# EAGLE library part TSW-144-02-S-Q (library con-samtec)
THROUGH-HOLE .025" SQ POST HEADER Source: Samtec TSW.pdf
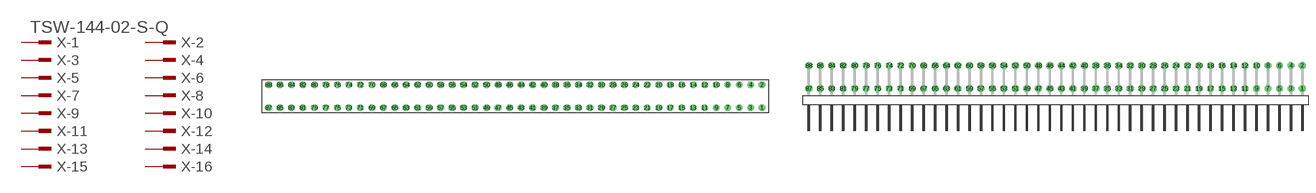
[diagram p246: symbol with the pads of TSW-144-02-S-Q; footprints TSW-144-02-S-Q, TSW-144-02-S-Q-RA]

Designator prefix X; gates -1=MPINV -2=MPIN -3=MPIN -4=MPIN -5=MPIN -6=MPIN -7=MPIN -8=MPIN -9=MPIN -10=MPIN -11=MPIN -12=MPIN -13=MPIN -14=MPIN -15=MPIN -16=MPIN -17=MPIN -18=MPIN -19=MPIN -20=MPIN -21=MPIN -22=MPIN -23=MPIN -24=MPIN -25=MPIN -26=MPIN -27=MPIN -28=MPIN -29=MPIN -30=MPIN -31=MPIN -32=MPIN -33=MPIN -34=MPIN -35=MPIN -36=MPIN -37=MPIN -38=MPIN -39=MPIN -40=MPIN -41=MPIN -42=MPIN -43=MPIN -44=MPIN -45=MPIN -46=MPIN -47=MPIN -48=MPIN -49=MPIN -50=MPIN -51=MPIN -52=MPIN -53=MPIN -54=MPIN -55=MPIN -56=MPIN -57=MPIN -58=MPIN -59=MPIN -60=MPIN -61=MPIN -62=MPIN -63=MPIN -64=MPIN -65=MPIN -66=MPIN -67=MPIN -68=MPIN -69=MPIN -70=MPIN -71=MPIN -72=MPIN -73=MPIN -74=MPIN -75=MPIN -76=MPIN -77=MPIN -78=MPIN -79=MPIN -80=MPIN -81=MPIN -82=MPIN -83=MPIN -84=MPIN -85=MPIN -86=MPIN -87=MPIN -88=MPIN

## TSW-144-02-S-Q (OC_FARNELL: unknown; OC_NEWARK: unknown)  [TSW-144-02-S-Q]
1  -1:1  pas
2  -2:1  pas
3  -3:1  pas
4  -4:1  pas
5  -5:1  pas
6  -6:1  pas
7  -7:1  pas
8  -8:1  pas
9  -9:1  pas
10  -10:1  pas
11  -11:1  pas
12  -12:1  pas
13  -13:1  pas
14  -14:1  pas
15  -15:1  pas
16  -16:1  pas
17  -17:1  pas
18  -18:1  pas
19  -19:1  pas
20  -20:1  pas
21  -21:1  pas
22  -22:1  pas
23  -23:1  pas
24  -24:1  pas
25  -25:1  pas
26  -26:1  pas
27  -27:1  pas
28  -28:1  pas
29  -29:1  pas
30  -30:1  pas
31  -31:1  pas
32  -32:1  pas
33  -33:1  pas
34  -34:1  pas
35  -35:1  pas
36  -36:1  pas
37  -37:1  pas
38  -38:1  pas
39  -39:1  pas
40  -40:1  pas
41  -41:1  pas
42  -42:1  pas
43  -43:1  pas
44  -44:1  pas
45  -45:1  pas
46  -46:1  pas
47  -47:1  pas
48  -48:1  pas
49  -49:1  pas
50  -50:1  pas
51  -51:1  pas
52  -52:1  pas
53  -53:1  pas
54  -54:1  pas
55  -55:1  pas
56  -56:1  pas
57  -57:1  pas
58  -58:1  pas
59  -59:1  pas
60  -60:1  pas
61  -61:1  pas
62  -62:1  pas
63  -63:1  pas
64  -64:1  pas
65  -65:1  pas
66  -66:1  pas
67  -67:1  pas
68  -68:1  pas
69  -69:1  pas
70  -70:1  pas
71  -71:1  pas
72  -72:1  pas
73  -73:1  pas
74  -74:1  pas
75  -75:1  pas
76  -76:1  pas
77  -77:1  pas
78  -78:1  pas
79  -79:1  pas
80  -80:1  pas
81  -81:1  pas
82  -82:1  pas
83  -83:1  pas
84  -84:1  pas
85  -85:1  pas
86  -86:1  pas
87  -87:1  pas
88  -88:1  pas

## TSW-144-02-S-Q-RA (OC_FARNELL: unknown; OC_NEWARK: unknown)  [TSW-144-02-S-Q-RA]
Pads as for TSW-144-02-S-Q

## Footprint TSW-144-02-S-Q (pad centres in mm)
THROUGH-HOLE .025" SQ POST HEADER Source: Samtec TSW.pdf
drill 1 pad 1.5 octagon: 1 54.61,-2.54; 2 54.61,2.54; 3 52.07,-2.54; 4 52.07,2.54; 5 49.53,-2.54; 6 49.53,2.54; 7 46.99,-2.54; 8 46.99,2.54; 9 44.45,-2.54; 10 44.45,2.54; 11 41.91,-2.54; 12 41.91,2.54; 13 39.37,-2.54; 14 39.37,2.54; 15 36.83,-2.54; 16 36.83,2.54; 17 34.29,-2.54; 18 34.29,2.54; 19 31.75,-2.54; 20 31.75,2.54; 21 29.21,-2.54; 22 29.21,2.54; 23 26.67,-2.54; 24 26.67,2.54; 25 24.13,-2.54; 26 24.13,2.54; 27 21.59,-2.54; 28 21.59,2.54; 29 19.05,-2.54; 30 19.05,2.54; 31 16.51,-2.54; 32 16.51,2.54; 33 13.97,-2.54; 34 13.97,2.54; 35 11.43,-2.54; 36 11.43,2.54; 37 8.89,-2.54; 38 8.89,2.54; 39 6.35,-2.54; 40 6.35,2.54; 41 3.81,-2.54; 42 3.81,2.54; 43 1.27,-2.54; 44 1.27,2.54; 45 -1.27,-2.54; 46 -1.27,2.54; 47 -3.81,-2.54; 48 -3.81,2.54; 49 -6.35,-2.54; 50 -6.35,2.54; 51 -8.89,-2.54; 52 -8.89,2.54; 53 -11.43,-2.54; 54 -11.43,2.54; 55 -13.97,-2.54; 56 -13.97,2.54; 57 -16.51,-2.54; 58 -16.51,2.54; 59 -19.05,-2.54; 60 -19.05,2.54; 61 -21.59,-2.54; 62 -21.59,2.54; 63 -24.13,-2.54; 64 -24.13,2.54; 65 -26.67,-2.54; 66 -26.67,2.54; 67 -29.21,-2.54; 68 -29.21,2.54; 69 -31.75,-2.54; 70 -31.75,2.54; 71 -34.29,-2.54; 72 -34.29,2.54; 73 -36.83,-2.54; 74 -36.83,2.54; 75 -39.37,-2.54; 76 -39.37,2.54; 77 -41.91,-2.54; 78 -41.91,2.54; 79 -44.45,-2.54; 80 -44.45,2.54; 81 -46.99,-2.54; 82 -46.99,2.54; 83 -49.53,-2.54; 84 -49.53,2.54; 85 -52.07,-2.54; 86 -52.07,2.54; 87 -54.61,-2.54; 88 -54.61,2.54

## Footprint TSW-144-02-S-Q-RA (pad centres in mm)
THROUGH-HOLE .025" SQ POST HEADER Source: Samtec TSW.pdf
drill 1 pad 1.5 octagon: 1 54.61,1.524; 2 54.61,6.604; 3 52.07,1.524; 4 52.07,6.604; 5 49.53,1.524; 6 49.53,6.604; 7 46.99,1.524; 8 46.99,6.604; 9 44.45,1.524; 10 44.45,6.604; 11 41.91,1.524; 12 41.91,6.604; 13 39.37,1.524; 14 39.37,6.604; 15 36.83,1.524; 16 36.83,6.604; 17 34.29,1.524; 18 34.29,6.604; 19 31.75,1.524; 20 31.75,6.604; 21 29.21,1.524; 22 29.21,6.604; 23 26.67,1.524; 24 26.67,6.604; 25 24.13,1.524; 26 24.13,6.604; 27 21.59,1.524; 28 21.59,6.604; 29 19.05,1.524; 30 19.05,6.604; 31 16.51,1.524; 32 16.51,6.604; 33 13.97,1.524; 34 13.97,6.604; 35 11.43,1.524; 36 11.43,6.604; 37 8.89,1.524; 38 8.89,6.604; 39 6.35,1.524; 40 6.35,6.604; 41 3.81,1.524; 42 3.81,6.604; 43 1.27,1.524; 44 1.27,6.604; 45 -1.27,1.524; 46 -1.27,6.604; 47 -3.81,1.524; 48 -3.81,6.604; 49 -6.35,1.524; 50 -6.35,6.604; 51 -8.89,1.524; 52 -8.89,6.604; 53 -11.43,1.524; 54 -11.43,6.604; 55 -13.97,1.524; 56 -13.97,6.604; 57 -16.51,1.524; 58 -16.51,6.604; 59 -19.05,1.524; 60 -19.05,6.604; 61 -21.59,1.524; 62 -21.59,6.604; 63 -24.13,1.524; 64 -24.13,6.604; 65 -26.67,1.524; 66 -26.67,6.604; 67 -29.21,1.524; 68 -29.21,6.604; 69 -31.75,1.524; 70 -31.75,6.604; 71 -34.29,1.524; 72 -34.29,6.604; 73 -36.83,1.524; 74 -36.83,6.604; 75 -39.37,1.524; 76 -39.37,6.604; 77 -41.91,1.524; 78 -41.91,6.604; 79 -44.45,1.524; 80 -44.45,6.604; 81 -46.99,1.524; 82 -46.99,6.604; 83 -49.53,1.524; 84 -49.53,6.604; 85 -52.07,1.524; 86 -52.07,6.604; 87 -54.61,1.524; 88 -54.61,6.604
